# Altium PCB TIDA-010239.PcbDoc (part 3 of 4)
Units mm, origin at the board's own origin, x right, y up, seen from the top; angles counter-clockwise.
Board outline 160 x 175 mm, 4 copper layers (Top Layer, Inside 1, Inside 2, Bottom Layer), stack 1.787 mm thick; 299 components, 146 nets, 710 pads, 164 vias.
Unrouted connection lines stored in the file: 9.
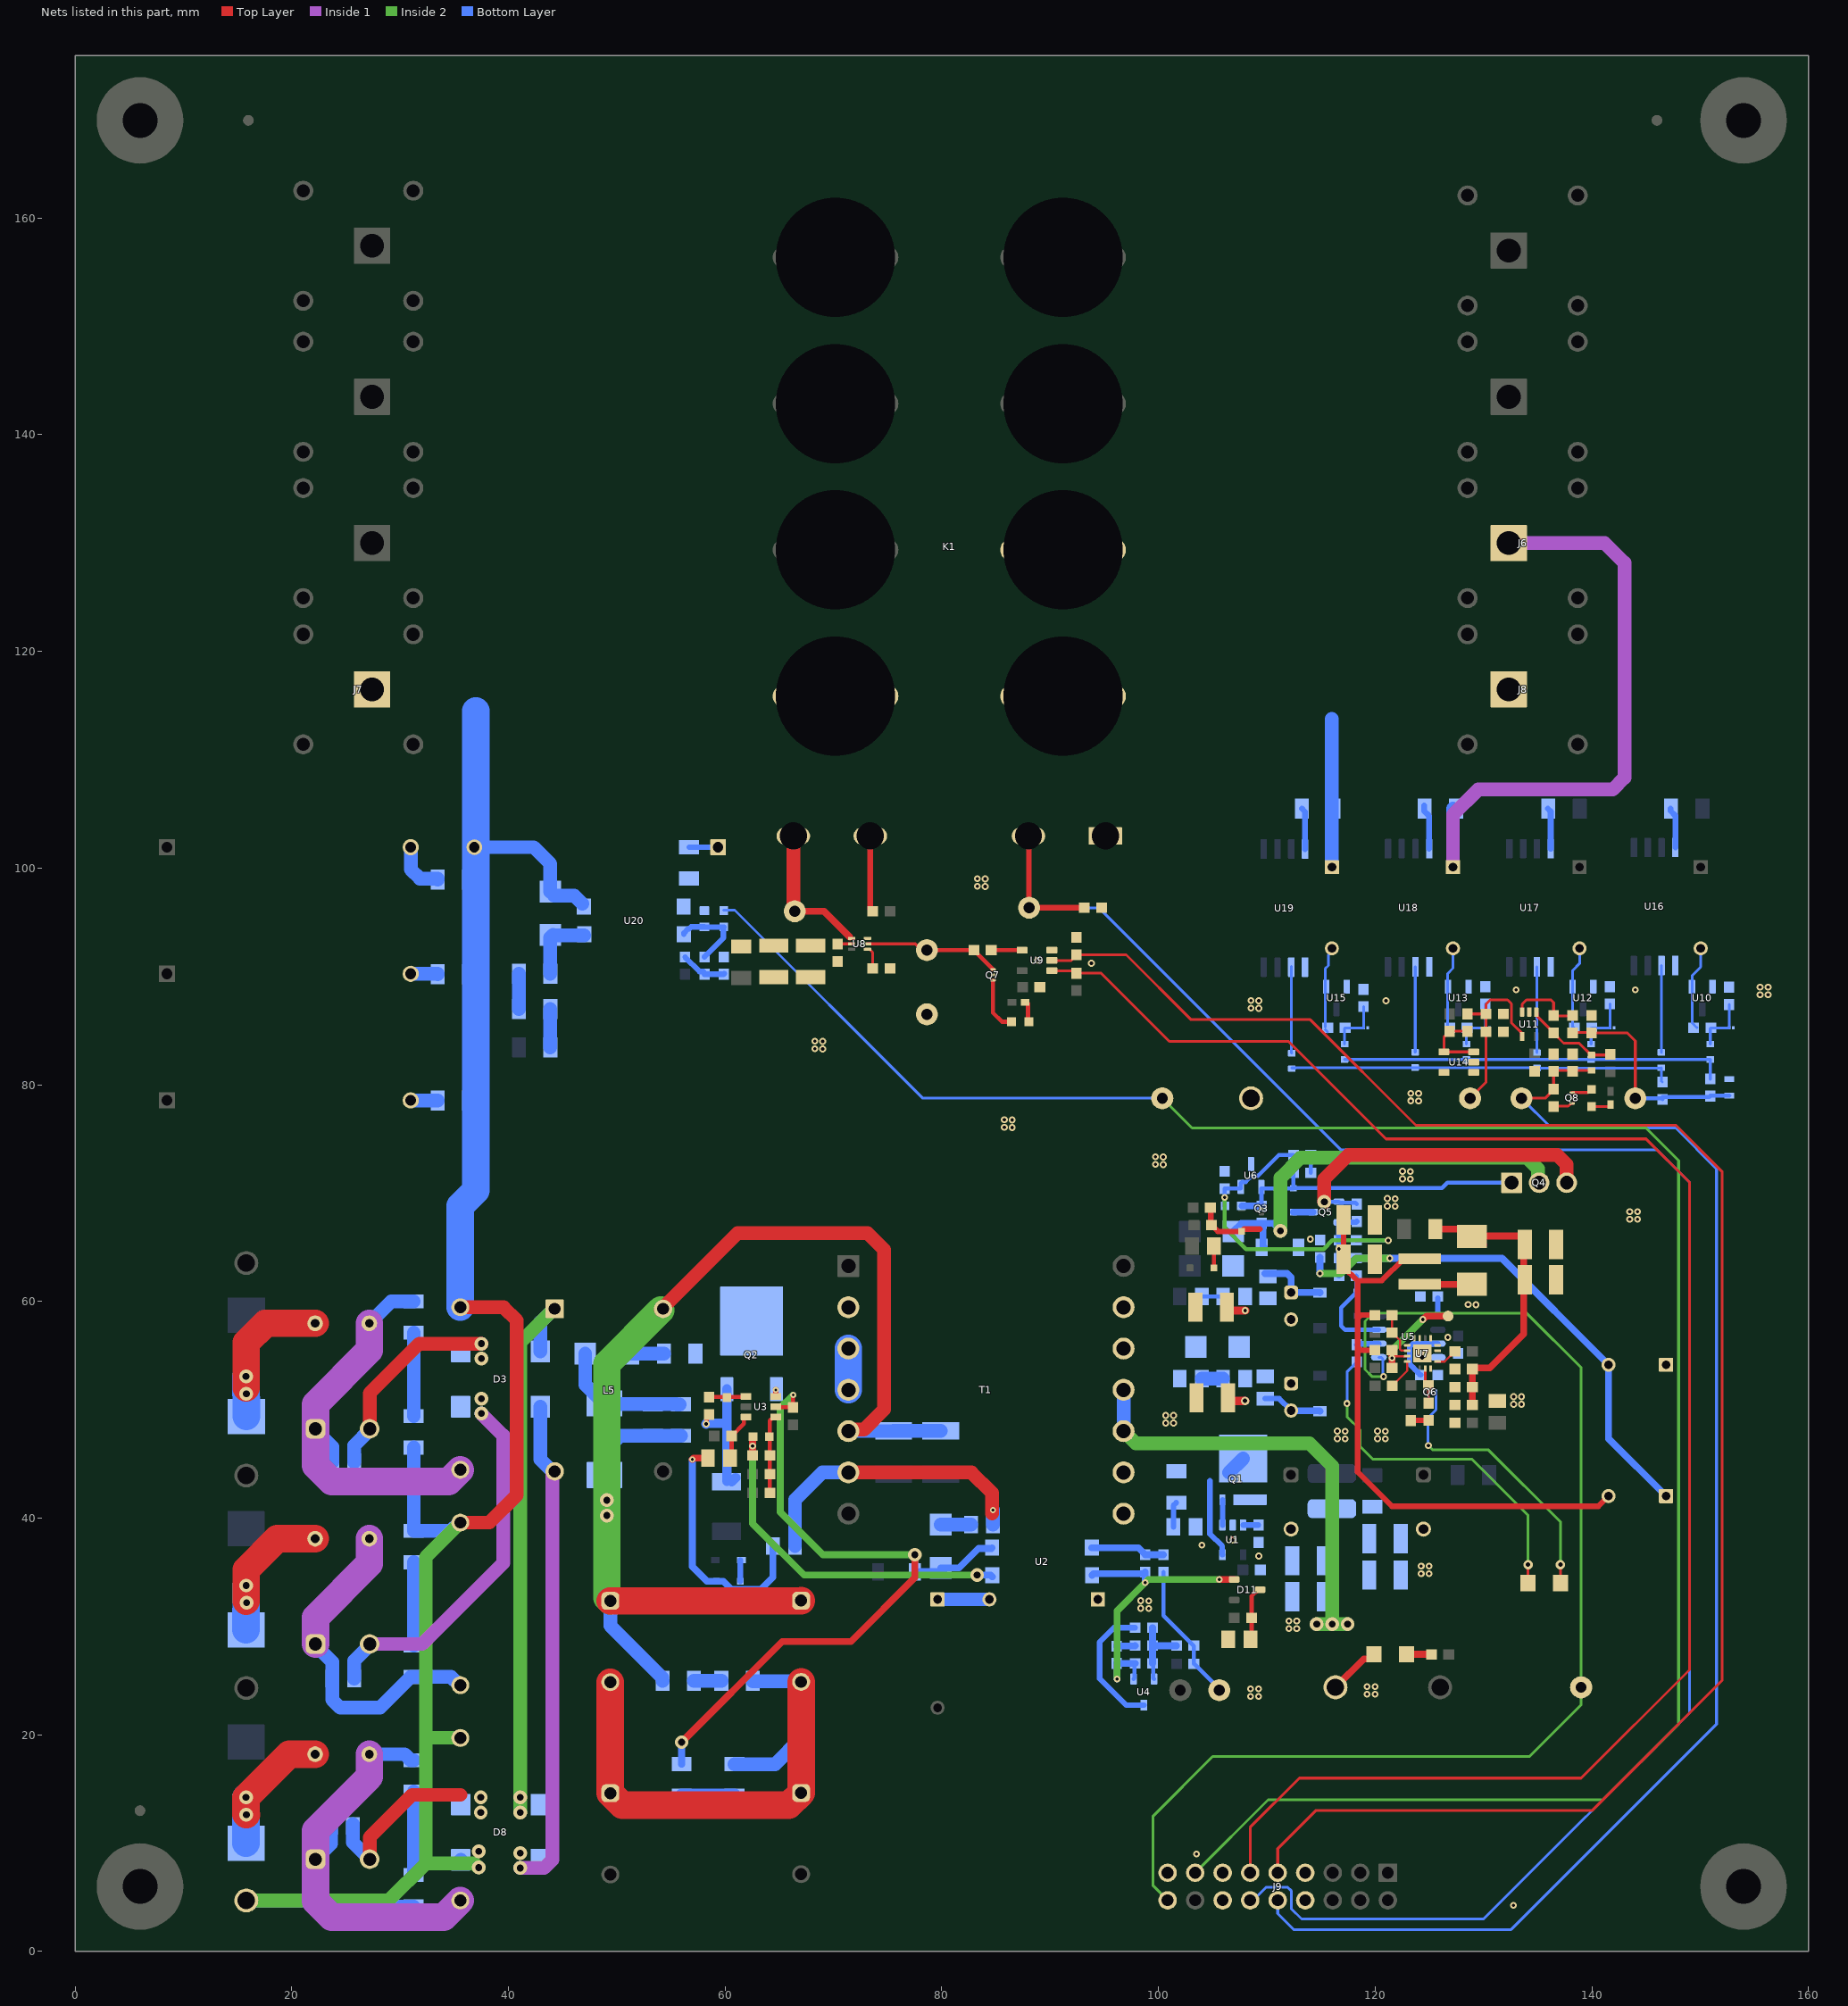
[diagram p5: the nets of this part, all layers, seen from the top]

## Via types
v1: diameter 0.635, hole 0.305, Top Layer to Bottom Layer, tented both sides, 118 vias
v2: diameter 1.27, hole 0.635, Top Layer to Bottom Layer, tented both sides, 35 vias
v3: diameter 0.762, hole 0.406, Top Layer to Bottom Layer, tented both sides, 4 vias
v4: diameter 0.559, hole 0.254, Top Layer to Bottom Layer, tented both sides, 4 vias
v5: diameter 0.864, hole 0.406, Top Layer to Bottom Layer, tented both sides, 3 vias

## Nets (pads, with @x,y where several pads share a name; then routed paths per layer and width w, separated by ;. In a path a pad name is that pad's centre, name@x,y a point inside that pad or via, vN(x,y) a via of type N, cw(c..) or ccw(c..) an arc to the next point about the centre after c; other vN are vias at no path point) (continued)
LINE3_OUT: C69.1 J6.1 K1.3 R89.2 | length 58.7
  Inside 1 w1.27: C69.1@127.176,100.08 127.176,104.926 129.5,107.25 141.922,107.25 143,108.328 143,128.172 141.182,129.99 J6.1@132.322,129.99
  Bottom Layer w1.27: C69.1@127.176,100.08 R89.2@127.176,105.474
MIRROR_IN: K1.11 R57.2 | length 7.1
  Top Layer w0.508: K1.11@73.394,102.958 73.394,96.228 R57.2@73.622,96 R57.2@73.612,96.01
N_IN: C9.2 C15.2 C20.2 C57.2 D8.3 D35.2 J7.1 K1.9 R7.1 R12.1 R19.1 R59.1 R60.1 R61.1 TP5.1 U20.2 | length 184.6
  Top Layer w1.27: C15.2@35.563,39.585 38.238,39.585 40.773,42.12 40.773,58.25 39.563,59.46 C9.2@35.563,59.46
  Inside 2 w1.27: TP5.1@15.817,4.723 28.973,4.723 ; 28.963,4.713 28.973,4.723 ; C20.2@35.563,19.71 32.378,19.75 ; C15.2@35.563,39.585 32.378,36.4 32.378,19.75 ; C15.2@35.567,39.585 C15.2@35.567,39.598 ; v2(37.25,7.75) 36.872,8.128 32.378,8.128 ; 28.973,4.723 32.378,8.128 ; 32.378,8.128 32.378,19.75
  Bottom Layer w1.27: TP5.1@15.813,4.71 23.253,4.71 23.803,4.16 R19.1@31.263,4.16 ; R7.1@31.263,46.52 R12.1@31.263,38.83 34.706,38.83 35.461,39.585 C15.2@35.563,39.585 ; D8.3@35.598,8.46 35.598,8.393 D8.3@35.863,8.128 ; C57.2@37,101.918 42.332,101.918 43.864,100.386 D35.2@43.864,97.822 44.229,97.457 46.06,97.457 U20.2@46.804,96.713
  Bottom Layer w2.54: C9.2@35.563,59.46 35.563,68.813 37,70.25 37,101.918 37,114.5
  other v2: 37.25,9.25
N_OUT: C71.1 J8.1 K1.2 R90.2 | length 13.7
  Bottom Layer w1.27: C71.1@116,100.08 116,113.75
NetC1_1: C1.1 C5.1 D1.1 L1.1 | length 1.4
  Top Layer w0.762: C5.1@106.599,59.164 v1(107.989,59.164)
NetC1_2: C1.2 R1.2 | length 2
  Bottom Layer w0.381: R1.2@103.989,60.45 C1.2@105.957,60.45
NetC2_1: C2.1 C3.2 | length 4.8
  Bottom Layer w1.27: C2.1@79.6,32.5 C3.2@84.4,32.5
NetC4_1: C4.1 D2.2 L1.2 | length 6.6
  Top Layer w0.635: C4.1@112.233,60.83 C4.1@112.238,60.835
  Bottom Layer w0.635: L1.2@109.833,62.576 111.861,62.576 112.233,62.204 C4.1@112.233,60.83 112.248,60.816 114.889,60.816 D2.2@114.903,60.801
NetC6_1: C6.1 C7.1 C8.1 C13.1 C14.1 D4.2 L5.4 R4.2 R5.2 T1.5 | length 121.3
  Top Layer w1.27: L5.4@54.063,59.21 61.147,66.294 73.152,66.294 74.676,64.77 74.676,50.038 72.812,48.174 71.517,48.174 T1.5@71.373,48.03
  Top Layer w2.54: C13.1@49.403,32.36 66.987,32.36 C14.1@67.013,32.386
  Inside 2 w2.54: C13.1@49.403,32.36 49.083,32.68 v2(49.083,41.652) 49.083,54.23 L5.4@54.063,59.21
  Bottom Layer w1.27: v2(49.083,40.244) v2(49.083,41.652) 49.083,43.502 48.873,43.712 48.963,43.801 48.963,46.27 50.293,47.6 R4.2@55.918,47.6 ; C13.1@49.403,32.36 49.403,30.068 54.21,25.261 54.21,24.986 R5.2@54.225,24.971 ; T1.5@71.373,48.03 71.38,48.037 C7.1@75.551,48.037 ; C7.1@75.551,48.044 C6.1@79.891,48.044
NetC8_2: C8.2 D4.1 D7.1 R4.1 | length 12
  Bottom Layer w1.27: D7.1@47.083,55.17 47.083,52.311 D4.1@48.575,50.819 ; D4.1@48.873,50.849 49.207,50.515 53.163,50.515 55.514,50.515 55.529,50.5 R4.1@55.804,50.5
NetC9_1: C9.1 L2.1 R2.2 R3.1 RT1.2 | length 38.2
  Inside 1 w2.54: RT1.2@27.163,57.98 27.163,55.48 22.193,50.51 22.193,44.868 23.681,43.38 34.483,43.38 C9.1@35.563,44.46
  Bottom Layer w1.27: L2.1@22.193,48.24 22.193,48.137 23.737,46.593 R3.1@23.737,45.18 ; RT1.2@27.198,58.014 29.193,60.01 R2.2@31.263,60.01
NetC10_2: C10.2 C11.1 D5.2 L3.1 | length 1.7
  Top Layer w0.762: C10.2@106.5,51.1 106.5,50.889 106.569,50.82 v3(107.989,50.82)
NetC11_2: C11.2 R6.2 | length 2
  Bottom Layer w1.27: R6.2@103.989,52.89 C11.2@105.957,52.89
NetC12_2: C12.2 D6.1 L3.2 | length 5.6
  Top Layer w0.635: C12.2@112.233,49.93 C12.2@112.238,49.925
  Bottom Layer w0.508: L3.2@109.833,51.034 111.129,51.034 C12.2@112.233,49.93
  Bottom Layer w0.635: C12.2@112.233,49.93 112.266,49.897 114.871,49.897 D6.1@114.903,49.865
NetC13_2: C13.2 C14.2 C16.1 C17.1 R8.1 R13.2 | length 55.9
  Top Layer w2.54: C13.2@49.403,24.86 C16.1@49.403,14.61 50.513,13.5 65.873,13.5 C17.1@67.013,14.64 C14.2@67.013,24.886
  Bottom Layer w1.27: R13.2@60.873,17.29 64.619,17.29 66.959,19.631 66.959,24.833 C14.2@67.013,24.886 66.97,24.929 62.574,24.929 62.559,24.944 R8.1@62.559,24.971
NetC15_1: C15.1 L4.1 R9.2 R10.1 RT2.2 | length 31.6
  Inside 1 w2.54: L4.1@22.193,28.38 22.193,30.83 27.163,35.8 RT2.2@27.163,38.1
  Bottom Layer w1.27: L4.1@22.193,28.38 22.193,28.277 23.737,26.733 R10.1@23.737,24.719 ; R10.1@23.737,25.2 23.737,23.246 24.483,22.5 28.148,22.5 R9.2@30.973,25.325 ; R9.2@30.988,25.34 34.706,25.34 35.461,24.585 C15.1@35.563,24.585
NetC19_1: C19.1 U1.3 | length 1.4
  Bottom Layer w0.508: U1.3@107.803,39.36 C19.1@109.223,39.36
NetC20_1: C20.1 L6.1 R15.1 R16.2 RT3.2 | length 38.5
  Inside 1 w2.54: RT3.2@27.163,18.21 27.163,16.12 22.193,11.15 22.193,4.663 23.681,3.175 34.028,3.175 C20.1@35.563,4.71
  Bottom Layer w1.27: L6.1@22.193,8.417 L6.1@22.193,8.52 23.617,9.944 R15.1@23.617,11.777 ; RT3.2@27.212,18.21 30.428,18.21 30.988,17.65 R16.2@31.263,17.65
NetC21_2: C21.2 C22.2 C23.2 C24.2 L7.1 R18.1 T1.10 T1.11 | length 41.9
  Inside 2 w1.27: T1.10@96.773,48.03 97.913,46.89 113.943,46.89 116.027,44.807 v2(116.027,30.208) ; v2(114.603,30.208) v2(116.027,30.208) ; v2(117.45,30.208) v2(116.027,30.208)
  Bottom Layer w1.27: T1.11@96.758,51.855 T1.11@96.773,51.84 T1.10@96.773,48.03
NetC27_1: C27.1 R23.1 | length 2.4
  Bottom Layer w0.508: C27.1@101.377,39.18 101.377,41.154 R23.1@101.643,41.42
NetC28_1: C28.1 C29.1 D11.1 R25.2 U2.2 U4.1 | length 29
  Top Layer w0.635: v1(105.603,34.34) D11.1@106.983,34.34
  Inside 2 w0.635: v1(96.162,25.144) 96.162,31.432 v1(98.775,34.046) 99.069,34.34 v1(105.603,34.34)
  Bottom Layer w0.381: U4.1@97.693,25.144 97.768,25.219 97.768,26.515 C28.1@97.838,26.585
  Bottom Layer w0.635: U2.2@93.862,34.73 94.008,34.875 R25.2@98.618,34.875 ; C29.1@96.123,26.59 C29.1@96.128,26.585 ; v1(96.162,25.144) 96.162,26.552 C29.1@96.128,26.585 ; C28.1@97.838,26.585 C29.1@96.128,26.585 ; R25.2@98.763,35.02 R25.2@98.618,34.875 ; v1(98.775,34.046) 98.775,34.838 98.738,34.875 R25.2@98.618,34.875
NetC28_2: C28.2 R28.1 R30.2 R33.2 U4.2 | length 7
  Bottom Layer w0.381: C28.2@99.443,26.58 99.518,26.505 99.518,25.219 U4.2@99.593,25.144
  Bottom Layer w0.635: C28.2@99.443,26.58 R30.2@99.443,28.22 ; R33.2@99.443,29.88 R30.2@99.443,28.22 ; R28.1@101.657,28.22 R30.2@99.443,28.22
NetC29_2: C29.2 R30.1 | length 1.7
  Bottom Layer w0.635: C29.2@96.123,28.19 96.138,28.205 97.828,28.205 R30.1@97.843,28.22
NetC30_1: C30.1 C32.1 D10.1 R17.1 U2.4 U3.2 | length 69.8
  Top Layer w0.381: U3.2@64.678,50.28 64.713,50.245 66.238,50.245 C32.1@66.273,50.21 v4(66.273,51.36)
  Top Layer w0.635: v2(55.983,19.32) 65.283,28.62 71.613,28.62 77.513,34.52 v2(77.513,36.62)
  Inside 2 w0.635: v4(66.273,51.36) 65.088,50.175 65.088,40.545 69.013,36.62 v2(77.513,36.62)
  Bottom Layer w0.635: R17.1@55.983,17.29 v2(55.983,19.32) ; v2(77.513,36.62) C30.1@77.513,35.05 D10.1@80.193,35.05 ; D10.1@79.9,35.4 81.6,35.4 83.407,37.207 84.574,37.207 U2.4@84.637,37.27
NetC31_1: C31.1 D11.3 R31.2 | length 5.1
  Top Layer w0.381: C31.1@108.475,28.8 108.593,28.918 R31.2@108.593,30.81 108.593,32.8 109.183,33.39 D11.3@109.383,33.39
NetC33_1: C33.1 R34.1 U3.4 | length 3.4
  Top Layer w0.381: R34.1@58.524,51.17 58.554,51.2 61.898,51.2 U3.4@61.928,51.23
NetC34_1: C34.1 R36.2 U2.3 | length 33.1
  Top Layer w0.635: R36.2@62.533,45.792 v1(62.533,46.656) C34.1@62.533,47.52
  Inside 2 w0.635: v1(62.533,46.656) 62.533,39.5 67.288,34.745 v2(83.255,34.745)
  Bottom Layer w0.635: v2@83.25,34.75 83.26,34.74 84.503,34.74 U2.3@84.662,34.58
NetC34_2: C34.2 C35.2 R36.1 R37.2 U3.1 | length 7.3
  Top Layer w0.381: C35.2@64.133,42.33 R37.2@64.133,44.06 64.133,47.52 64.133,48.985 64.478,49.33 U3.1@64.678,49.33
NetC37_1: C37.1 D16.1 Q4.2 R40.1 | length 38.8
  Inside 2 w1.27: v2(111.253,66.52) 111.253,71.403 113.101,73.25 134.014,73.25 135.007,72.257 135.007,71.076 Q4.2@135.128,70.955
  Bottom Layer w0.635: D16.1@106.895,66.454 107.651,67.21 R40.1@109.503,67.21 ; C37.1@109.763,64.98 109.633,65.11 109.633,67.08 R40.1@109.503,67.21 ; v2@111.273,66.21 111.162,66.321 111.162,66.656 110.608,67.21 R40.1@109.503,67.21
NetC38_1: C38.1 D17.2 Q4.1 R40.2 R44.1 U6.1 | length 28.2
  Bottom Layer w0.381: R40.2@109.503,68.81 109.498,68.815 109.498,70.405 109.493,70.41 109.513,70.43 112.423,70.43 D17.2@112.443,70.45 ; R44.1@112.453,71.88 112.448,71.875 112.448,70.455 D17.2@112.443,70.45 ; Q4.1@132.588,70.955 126.669,70.955 126.163,70.45 D17.2@112.443,70.45
  Bottom Layer w0.635: C38.1@107.699,68.81 R40.2@109.503,68.81
NetC38_2: C38.2 C39.2 R43.2 R48.2 U6.2 | length 31.5
  Inside 2 w0.381: v1(106.099,69.61) 106.099,66.825 108.088,64.835 115.232,64.835 116.027,65.63 v1(121.202,65.63)
  Bottom Layer w0.381: C38.2@106.099,68.81 v1(106.099,69.61) R48.2@106.099,70.41 107.593,70.41 107.593,70.91 107.703,71.02 108.06,71.02 108.641,71.601 109.204,71.601 111.103,73.5 C39.2@112.453,73.5 ; R43.2@118.253,65.63 v1(121.202,65.63)
NetC39_1: C39.1 R44.2 | length 1.6
  Bottom Layer w0.381: R44.2@114.053,71.88 C39.1@114.053,73.5
NetC40_1: C40.1 C42.2 R46.1 R47.2 | length 50.2
  Inside 2 w0.635: v1(114.903,62.576) 116.829,62.576 118.233,63.98 v1(121.334,63.98)
  Bottom Layer w0.635: v1(114.903,62.576) R47.2@114.903,64.06 ; R46.1@118.253,63.98 v1(121.334,63.98) 131.703,63.98 C42.2@141.533,54.15 141.533,47.33 C40.1@146.833,42.03
NetC41_1: C41.1 U5.3 | length 5.7
  Bottom Layer w0.508: C41.1@124.183,53.22 124.158,53.22 123.937,53.441 123.937,53.466 123.173,54.23 123.173,55.784 123.482,56.092 125.766,56.092 U5.3@125.783,56.11
NetC44_1: C44.1 U5.1 | length 1.6
  Bottom Layer w0.508: U5.1@125.783,58.65 C44.1@125.783,60.296
NetC47_2: C47.2 R49.1 U7.2 | length 4.2
  Top Layer w0.203: R49.1@121.553,58.74 C47.2@121.553,57.119 121.578,57.119 122.282,56.415 122.282,55.587 122.401,55.468 122.935,55.468 U7.2@122.953,55.45
NetC48_2: C48.2 C49.2 C50.1 D20.1 L9.1 R51.2 R52.2 | length 28.2
  Top Layer w0.635: L9.1@125.553,66.67 128.293,66.67 128.923,66.04 133.567,66.04 133.7,65.908 133.7,65.25 133.7,62 133.7,56.987 130.579,53.866 129.069,53.866 C50.1@128.963,53.76 ; D20.1@128.926,66.005 129.688,65.243 D20.1@130.007,65.243 ; R52.2@128.963,50.43 R51.2@128.963,52.094 C50.1@128.963,53.76 ; C50.1@128.988,53.76 C50.1@128.963,53.76
NetC50_2: C50.2 R51.1 R52.1 R56.2 U7.8
NetC51_1: C51.1 R53.2 U7.7 | length 3.3
  Top Layer w0.254: U7.7@124.603,53.8 124.603,52.614 C51.1@124.913,52.266 124.919,51.918 124.919,50.986 R53.2@124.944,50.613
NetC52_1: C52.1 U7.4 | length 2.8
  Top Layer w0.203: C52.1@121.583,52.256 121.608,52.256 122.953,53.601 U7.4@122.953,54.45
NetC53_2: C53.2 R53.1 | length 1.7
  Top Layer w0.508: C53.2@123.273,49.006 123.276,49.01 124.941,49.01 R53.1@124.944,49.013
NetC54_2: C54.2 R59.2 | length 5
  Bottom Layer w1.27: C54.2@30.984,101.918 30.984,99.868 31.832,99.02 33.457,99.02 33.472,99.005 R59.2@33.472,98.93
NetC55_2: C55.2 R60.2 | length 2.5
  Bottom Layer w1.27: C55.2@30.984,90.234 33.457,90.234 33.472,90.219 R60.2@33.472,90.18
NetC56_2: C56.2 R61.2 | length 2.5
  Bottom Layer w1.27: C56.2@30.984,78.55 R61.2@33.472,78.55
NetC57_1: C57.1 R62.2 | length 2.8
  Bottom Layer w0.508: R62.2@56.672,101.93 56.678,101.924 59.346,101.924 C57.1@59.422,102
NetC58_2: C58.2 C59.2 C60.1 F4.1 U8.5 | length 1.3
  Top Layer w0.254: C60.1@70.4,92.976 70.424,93 U8.5@71.666,93
NetC62_2: C62.2 R68.1 U10.1 | length 7.8
  Bottom Layer w0.254: R68.1@149.697,85.275 149.672,85.275 149.247,85.7 149.247,88.925 149.247,90.075 150.036,90.864 C62.2@150.036,92.58
NetC63_1: C63.1 D22.2 D23.1 R68.2 | length 5.4
  Bottom Layer w0.254: D22.2@150.922,83.75 150.922,85.2 R68.2@150.972,85.25 D23.1@152.672,85.25 C63.1@152.672,87.4
NetC65_2: C65.2 R72.1 U12.1 | length 7.7
  Bottom Layer w0.254: R72.1@138.222,85.309 138.222,88.899 138.222,90.55 138.86,91.188 C65.2@138.86,92.58 ; R72.1@138.272,85.309 R72.1@138.417,85.164
NetC66_1: C66.1 R70.2 R71.1 R74.2 R75.2 TP18.1 | length 20.1
  Top Layer w0.254: R71.1@138.213,84.824 139.918,84.824 R75.2@139.963,84.779 143.263,84.779 144,84.041 TP18.1@144,78.75
  Bottom Layer w0.381: TP18.1@144,78.75 146.4,78.75 R74.2@146.5,78.65 ; R74.2@146.5,78.873 150.845,78.873 R70.2@150.922,78.95 ; R70.2@150.926,78.992 152.669,78.992 C66.1@152.672,78.988
NetC68_1: C68.1 D25.2 D26.1 R72.2 | length 5.4
  Bottom Layer w0.254: D25.2@139.922,83.75 139.922,85.2 R72.2@139.972,85.25 D26.1@141.672,85.25 C68.1@141.672,87.45
NetC69_2: C69.2 R77.1 U13.1 | length 7.8
  Bottom Layer w0.254: R77.1@126.822,85.09 126.672,85.24 126.672,88.825 126.672,90.25 127.176,90.754 C69.2@127.176,92.58
NetC70_1: C70.1 D27.2 D28.1 R77.2 | length 5.4
  Bottom Layer w0.254: D27.2@128.422,83.75 128.422,85.2 R77.2@128.472,85.25 D28.1@130.172,85.25 C70.1@130.172,87.45
NetC71_2: C71.2 R80.1 U15.1 | length 7.8
  Bottom Layer w0.254: R80.1@115.397,85.078 R80.1@115.597,84.878 ; R80.1@115.397,85.328 115.397,88.828 115.397,90.725 115.672,91 115.672,91.969 116,92.297 C71.2@116,92.58
NetC72_1: C72.1 D29.2 D30.1 R80.2 | length 5.2
  Bottom Layer w0.254: D29.2@117.172,83.75 117.172,85.2 R80.2@117.222,85.25 D30.1@118.922,85.25 C72.1@118.922,87.2
NetC74_1: C74.1 R39.1 R82.2 | length 4.1
  Bottom Layer w0.508: R39.1@56.31,91.796 56.31,91.771 57.639,90.442 R82.2@57.98,90.442 ; R82.2@58.088,90.196 C74.1@59.866,90.196 59.868,90.196 C74.1@59.922,90.25
NetC75_1: C75.1 R83.2 | length 3.6
  Bottom Layer w1.27: C75.1@43.864,83.434 R83.2@43.864,87.001
NetC76_1: C76.1 C77.2 R82.1 U20.4 | length 7.5
  Bottom Layer w0.508: U20.4@56.197,93.89 56.197,93.99 56.593,94.386 56.693,94.386 56.871,94.564 C77.2@58.088,94.564 58.113,94.539 59.883,94.539 59.842,94.498 59.842,93.55 58.334,92.042 58.309,92.042 58.088,91.821 R82.1@58.088,91.796
NetD3_1: D3.1 D8.1 L5.1 | length 51.9
  Inside 2 w1.27: v2(41.103,12.84) 41.103,56.25 L5.1@44.063,59.21
  Bottom Layer w1.27: D3.1@42.948,55.38 42.948,58.095 L5.1@44.063,59.21
  other v2: 41.103,14.22
NetD3_2: D3.2 D8.2 L5.2 | length 45.5
  Inside 1 w1.27: v2(41.103,7.71) 43.295,7.71 44.063,8.478 L5.2@44.063,44.21
  Bottom Layer w1.27: D3.2@42.948,50.28 42.948,45.414 44.063,44.299 L5.2@44.063,44.21
  other v2: 41.103,9.09
NetD3_3: D3.3 L4.2 R10.2 | length 33.8
  Inside 1 w1.27: L4.2@27.193,28.38 32.043,28.38 39.513,35.85 39.513,47.64 v2(37.503,49.65)
  Bottom Layer w1.27: R10.2@25.769,25.2 25.769,26.853 27.193,28.277 L4.2@27.193,28.38
  other v2: 37.503,51.03
NetD3_4: D3.4 L2.2 R3.2 | length 19.1
  Top Layer w1.27: L2.2@27.193,48.24 27.193,51.52 31.773,56.1 v2(37.503,56.1)
  Bottom Layer w1.27: R3.2@25.769,45.18 25.769,46.713 27.193,48.137 L2.2@27.193,48.24
  other v2: 37.503,54.72
NetD5_1: D5.1 R6.1 T1.12
NetD7_2: D7.2 R11.2 | length 3.3
  Bottom Layer w1.27: D7.2@51.083,55.17 R11.2@54.363,55.17
NetD8_4: D8.4 L6.2 R15.2 | length 16
  Top Layer w1.27: L6.2@27.193,8.52 27.193,10.54 31.113,14.46 35.563,14.46
  Bottom Layer w1.27: R15.2@25.649,11.777 25.649,10.064 L6.2@27.193,8.52 L6.2@27.193,8.417
  other v2: 37.443,12.84 37.443,14.22
NetD9_2: D9.2 R20.1 | length 2.3
  Top Layer w0.635: D9.2@122.888,27.432 R20.1@125.184,27.432
NetD10_2: D10.2 R24.1 | length 2.8
  Bottom Layer w1.27: D10.2@79.9,39.4 R24.1@82.684,39.4
NetD12_1: D12.1 R27.1 R29.2 | length 23
  Top Layer w0.635: v4(56.973,45.414) 57.099,45.54 R29.2@58.417,45.54
  Bottom Layer w0.635: v4(56.973,45.414) 56.973,35.527 58.33,34.17 59.83,34.17 60.574,33.426 63.301,33.426 64.417,34.542 R27.1@64.417,37.41
NetD12_2: D12.2 D13.2 | length 1.9
  Bottom Layer w0.508: D12.2@61.403,34.17 D13.2@61.403,36.12
NetD14_1: D14.1 R21.1 | length 2.1
  Top Layer w0.381: D14.1@105.113,63.09 105.113,64.854 R21.1@105.359,65.1
NetD17_1: D17.1 Q5.3 | length 1.8
  Bottom Layer w0.635: D17.1@112.443,68.25 Q5.3@114.243,68.25
NetD18_2: D18.2 R45.2 U5.7 | length 8.9
  Bottom Layer w0.381: R45.2@118.253,62.37 118.273,62.35 118.273,60.881 D18.2@118.293,60.861 116.853,59.421 116.853,57.75 117.223,57.38 U5.7@120.333,57.38
NetD19_1: D19.1 Q6.3@125.605,51.646 | length 26
  Top Layer w0.254: D19.1@137.1,34 v5(137.1,35.7)
  Inside 2 w0.254: v1(124.9,46.7) 124.908,46.7 125.316,46.292 130.458,46.292 137.1,39.65 v5(137.1,35.7)
  Bottom Layer w0.254: v1(124.9,46.7) 124.867,46.733 124.867,49.257 125.605,49.995 Q6.3@125.605,51.646
NetD19_2: D19.2 R41.1 | length 33.1
  Top Layer w0.254: D19.2@134.1,34 v5(134.1,35.7)
  Inside 2 w0.254: v1(117.396,50.579) 117.396,49.354 118.6,48.15 118.6,46.6 119.766,45.434 128.935,45.434 134.1,40.269 v5(134.1,35.7)
  Bottom Layer w0.254: v1(117.396,50.579) 117.396,53.489 118.293,54.385 R41.1@118.293,54.41
NetD20_2: D20.2 L8.2 U7.1 U7.15 U7.16 | length 4.9
  Top Layer w0.635: L8.2@124.103,61.575 128.968,61.575 D20.2@128.973,61.57
NetD21_1: D21.1 Q7.3@84.734,89.635 | length 5
  Top Layer w0.381: Q7.3@84.734,89.635 84.734,86.635 85.554,85.815 D21.1@86.437,85.815
NetD21_2: D21.2 R63.1 | length 1.9
  Top Layer w0.381: R63.1@87.876,87.6 87.957,87.519 87.957,85.895 D21.2@88.037,85.815
NetD22_1: D22.1 D25.1 D27.1 D29.1 R70.1 | length 35.6
  Bottom Layer w0.254: D29.1@117.172,82.33 D27.1@128.422,82.33 D25.1@139.922,82.33 D22.1@150.922,82.33 R70.1@150.922,80.505
NetD24_2: D24.2 R69.1 R76.1 U11.1 | length 8.7
  Top Layer w0.254: U11.1@134.863,86.704 134.936,86.631 134.936,86.331 136.463,84.804 R76.1@136.463,84.779 ; R76.1@136.463,84.754 137.388,83.829 138.823,83.829 139.913,82.739 D24.2@139.963,82.739 141.663,82.739 R69.1@141.713,82.789
NetD31_2: D31.2 U16.6 | length 8
  Bottom Layer w0.254: D31.2@146.422,82.96 U16.6@146.422,91
NetD32_2: D32.2 U17.6 | length 7.9
  Bottom Layer w0.254: D32.2@134.923,82.961 U17.6@134.923,90.88
NetD33_2: D33.2 U18.6 | length 7.9
  Bottom Layer w0.254: D33.2@123.672,83 123.693,83.021 123.693,90.861 U18.6@123.714,90.882
NetD34_2: D34.2 U19.6 | length 8
  Bottom Layer w0.254: U19.6@112.25,90.935 U19.6@112.25,90.85 112.275,90.825 112.275,82.935 D34.2@112.3,82.91
NetD35_1: D35.1 R84.1 U20.1 | length 6.6
  Bottom Layer w1.27: R84.1@43.864,90.234 43.864,93.568 44.118,93.822 44.145,93.795 U20.1@46.992,93.795
NetD36_1: D36.1 Q8.3@138.182,79.279 | length 1.9
  Top Layer w0.254: Q8.3@138.182,79.279 139.663,79.279 D36.1@139.963,79.579 ; D36.1@139.938,79.354 D36.1@139.963,79.329
NetD36_2: D36.2 R85.1 | length 1.8
  Top Layer w0.254: D36.2@139.963,77.979 141.54,77.979 141.713,78.152 R85.1@141.713,78.179
NetF1_1: F1.1 RT1.1 | length 15
  Top Layer w2.54: v2@15.798,52.035 15.798,56.205 17.573,57.98 RT1.1@22.163,57.98
  Bottom Layer w2.54: v2(15.783,53.07) F1.1@15.813,49.385
  other v2: 15.813,51.48
NetF2_1: F2.1 RT2.1 | length 14.6
  Top Layer w2.54: v2@15.798,32.325 15.798,35.235 18.663,38.1 RT2.1@22.163,38.1
  Bottom Layer w2.54: F2.1@15.783,29.69 v2(15.798,33.78)
  other v2: 15.828,32.19
NetF3_1: F3.1 RT3.1 | length 13.9
  Top Layer w2.54: v2(15.813,12.63) 15.783,12.66 v2(15.783,14.22) 19.773,18.21 RT3.1@22.163,18.21
  Bottom Layer w2.54: F3.1@15.783,9.995 v2(15.783,14.22)
NetQ1_4: Q1.4 U1.1 | length 2.3
  Bottom Layer w0.508: U1.1@105.903,39.36 Q1.4@105.903,41.7
NetQ1_5-6-7-8: Q1.5-6-7-8 R23.2 T1.8 T1.9 U1.5 | length 9.2
  Bottom Layer w0.508: 104.744,43.444 104.744,38.544 105.875,37.413 105.875,36.638 U1.5@105.903,36.61
  Bottom Layer w1.27: Q1.5-6-7-8@106.508,44.2 Q1.5-6-7-8@107.808,45.5
NetQ2_1: Q2.1 U3.3 | length 0.6
  Top Layer w0.508: U3.3@64.678,51.23 v4(64.678,51.84)
NetQ2_3: Q2.3 R34.2 R35.2 | length 11.9
  Top Layer w0.381: v1(58.244,48.698) 58.293,48.747 58.293,49.339 R34.2@58.524,49.57
  Bottom Layer w0.889: v1(58.244,48.698) 58.296,48.75 60.164,48.75 ; R35.2@60.164,43.411 60.164,48.75 ; Q2.3@60.164,51.9 60.164,48.75 ; R35.2@60.608,43.37 R35.2@60.963,43.726
NetQ2_4: Q2.4 R11.1 T1.2
NetQ4_3: Q4.3 Q5.1 R42.2 | length 30.5
  Top Layer w1.27: v2(115.304,69.2) 115.304,71.304 117.5,73.5 136.812,73.5 137.668,72.644 Q4.3@137.668,70.955
  Bottom Layer w0.381: v2(115.304,69.2) Q5.1@116.643,69.2 116.753,69.091 118.183,69.091 R42.2@118.293,68.98
NetQ8_1: Q8.1@138.182,78.279 R86.2 | length 1.8
  Top Layer w0.254: R86.2@136.463,78.024 137.811,78.024 138.066,78.279 Q8.1@138.182,78.279
NetR2_1: R2.1 R7.2 | length 7.7
  Bottom Layer w1.27: R7.2@31.263,49.42 R2.1@31.263,57.11
NetR5_1: R5.1 R8.2 | length 2.5
  Bottom Layer w1.27: R5.1@57.125,24.971 R8.2@59.659,24.971
NetR9_1: R9.1 R12.2 | length 7.7
  Bottom Layer w1.27: R9.1@31.263,28.24 R12.2@31.263,35.93
NetR13_1: R13.1 R17.2 | length 4.9
  Bottom Layer w1.27: R17.2@55.983,14.39 R13.1@60.873,14.39
NetR16_1: R16.1 R19.2 | length 7.7
  Bottom Layer w1.27: R19.2@31.263,7.06 R16.1@31.263,14.75
NetR22_1: R22.1 R26.2 R28.2 TP7.1 | length 13.1
  Bottom Layer w0.381: R26.2@100.443,35.02 100.443,31.009 103.257,28.195 R22.1@103.257,26.56 ; R22.1@103.257,26.56 103.282,26.56 105.603,24.239 TP7.1@105.603,24.12
NetR24_2: R24.2 R27.2 T1.6 | length 27.6
  Top Layer w1.27: T1.6@71.373,44.22 82.739,44.22 84.629,42.33 84.629,40.41
  Bottom Layer w1.27: R27.2@66.449,37.41 66.449,41.696 68.973,44.22 T1.6@71.373,44.22 ; R24.2@84.716,39.4 v4(84.716,40.75)
NetR25_1: R25.1 R26.1 U2.1 | length 6.9
  Bottom Layer w0.635: U2.1@93.837,37.27 98.138,37.27 98.763,36.645 R25.1@98.763,36.62 R26.1@100.443,36.62
NetR29_1: R29.1 R32.2 U3.6 | length 4.5
  Top Layer w0.381: R29.1@60.449,45.54 60.593,45.684 R32.2@60.593,47.58 60.618,47.58 61.74,48.702 61.74,49.221 61.85,49.33 U3.6@61.928,49.33
NetR41_2: R41.2 U5.6 | length 2.1
  Bottom Layer w0.508: R41.2@118.293,56.01 118.375,56.092 120.316,56.092 U5.6@120.333,56.11
NetR50_1: R50.1 R54.2 TP11.1 U7.3 | length 9.7
  Top Layer w0.203: v1@121.553,54.95 U7.3@122.953,54.95
  Top Layer w0.635: R54.2@121.553,53.88 v1(121.553,54.759) v1@121.553,54.95 ; v1(124.397,58.33) 124.717,58.65 TP11.1@126.723,58.65
  Inside 2 w0.635: v1(121.553,54.759) 121.553,55.486 v1(124.397,58.33)
NetR55_2: R55.2 U7.9 | length 2
  Top Layer w0.203: U7.9@125.753,54.45 126.408,54.45 127.338,55.38 R55.2@127.363,55.38
NetR64_1: R64.1 U8.1 | length 2.1
  Top Layer w0.254: U8.1@73.146,92.5 73.331,92.5 73.622,92.209 R64.1@73.622,90.75
NetR67_1: R67.1 U9.4 | length 2.9
  Top Layer w0.381: R67.1@84.556,92.43 84.561,92.425 87.406,92.425 U9.4@87.411,92.42
NetR71_2: R71.2 R76.2 U11.3 | length 6.9
  Top Layer w0.254: U11.3@133.563,86.704 133.563,87.429 133.963,87.829 136.213,87.829 136.463,87.579 R76.2@136.463,86.379 136.508,86.334 R71.2@138.213,86.334
NetR78_1: R78.1 R79.2 U14.3 U14.4 | length 6.5
  Top Layer w0.254: R79.2@128.507,84.929 R78.1@126.86,84.929 126.86,84.904 126.338,84.381 U14.4@126.338,83.029 U14.3@129.088,83.029
NetR83_1: R83.1 R84.2 | length 3.2
  Bottom Layer w1.27: R83.1@40.964,87.001 R84.2@40.964,90.234
NetR87_1: R87.1 U16.4 | length 3.8
  Bottom Layer w0.54: R87.1@147.25,105.5 147.25,105.275 147.692,104.833 U16.4@147.692,101.9
NetR88_1: R88.1 U17.4 | length 3.8
  Bottom Layer w0.54: R88.1@135.932,105.474 136.193,105.213 U17.4@136.193,101.78
NetR89_1: R89.1 U18.4 | length 4.2
  Bottom Layer w0.54: R89.1@124.5,105.75 124.5,105.275 124.984,104.791 U18.4@124.984,101.782
NetR90_1: R90.1 U19.4 | length 3.9
  Bottom Layer w0.54: R90.1@113.222,105.5 113.52,105.202 U19.4@113.52,101.75
NetT1_3: T1.3 T1.4 | length 3.8
  Bottom Layer w2.54: T1.4@71.373,51.84 T1.3@71.373,55.65
PGND: C3.1 C4.2 C5.2 C10.1 C12.1 C18.2 C19.2 C21.1 C22.1 C23.1 C24.1 C25.2 C26.2 C27.2 C31.2 C36.2 C37.2 C41.2 C42.1 C43.2 C44.2 C45.1 C46.1 C48.1 C49.1 C58.1 C59.1 C60.2 C61.2 C63.2 C64.2 C66.2 C67.2 C68.2 C70.2 C72.2 C73.2 C74.2 C77.1 D9.1 D15.2 D23.2 D26.2 D28.2 D30.2 J9.7 J9.8 J9.13 J9.14 J9.17 K1.1 NT1.2 Q1.1-2-3 Q3.2@109.503,68.56 Q6.2@125.105,51.646 Q7.2@84.734,90.135 Q8.2@138.182,78.779 R33.1 R38.1 R47.1 R48.1 R58.2 R62.1 R64.2 R66.1 R73.1 R75.1 R81.1 T1.13 TP8.1 TP9.1 TP22.1 U1.2 U4.3 U5.4 U6.3 U7.11 U7.12 U7.13 U7.17@124.353,55.2 U8.3 U9.3 U10.2 U11.2 U12.2 U13.2 U14.1 U14.2 U14.5 U15.2 U16.5 U17.5 U18.5 U19.5 U20.3 | length 23.6
  Top Layer w0.508: C36.2@104.783,68.67 104.829,68.625 104.829,67.088 R38.1@104.874,67.042 104.899,67.042 105.481,66.46 D15.2@107.673,66.46 107.883,66.67 109.353,66.67
  Top Layer w0.635: TP8.1@116.332,24.384 118.947,26.999 119.505,26.999 119.888,27.382 D9.1@119.888,27.432
  Bottom Layer w0.508: R33.1@97.843,29.88 95.88,29.88 94.56,28.56 94.56,25.19 97.006,22.744 U4.3@98.643,22.744
  other v1: 132.75,4.25 103.5,9 108.5,23.552 109.229,23.541 119.25,23.75 119.979,23.739 109.229,24.242 108.5,24.25 119.979,24.44 119.25,24.448 112.75,29.799 112.021,29.81 112.021,30.508 112.75,30.5 98.361,31.677 99.09,31.666 99.09,32.367 98.361,32.375 124.968,34.859 124.239,34.87 124.239,35.568 124.968,35.56 109.25,36.5 104,37.5 106.853,37.985 116.494,47.332 117.223,47.321 120.213,47.332 120.942,47.321 116.494,48.03 117.223,48.022 120.213,48.03 120.942,48.022 100.66,48.78 101.389,48.769 100.66,49.478 101.389,49.47 133.5,50.5 132.771,50.511 132.771,51.209 133.5,51.201 126.693,56.68 129.3,59.7 128.571,59.708 114,65.75 144.215,67.576 143.486,67.587 143.486,68.285 144.215,68.277 121.847,68.786 121.118,68.797 121.118,69.495 121.847,69.487 122.521,71.31 123.25,71.299 122.521,72.008 123.25,72 99.714,72.645 100.443,72.635 100.443,73.335 99.714,73.343 85.771,76.06 86.5,76.049 85.771,76.758 86.5,76.75 123.271,78.511 124,78.5 123.271,79.209 124,79.201 69,83.299 68.271,83.31 68.271,84.008 69,84 109.25,87.049 108.521,87.06 108.521,87.758 109.25,87.75 121,87.75 156.25,88.299 155.521,88.31 133,88.75 144,88.75 155.521,89.008 156.25,89 93.8,91.2 88.786,91.47 83.271,98.31 84,98.299 83.271,99.008 84,99
  other v3: 124.316,54.84
PLC_ZC_IN: C76.2 J9.15 TP15.1 | length 200
  Inside 2 w0.254: TP15.1@100.348,78.75 103.098,76 145,76 148,73 148,21 141,14 110.11,14 J9.15@103.38,7.27
  Bottom Layer w0.254: C76.2@59.866,96.114 60.886,96.114 78.25,78.75 TP15.1@100.348,78.75
R_ENABLE: J9.9 R66.2 U9.2 | length 167
  Top Layer w0.254: U9.2@90.161,91.47 91.944,91.47 92.434,91.96 R66.2@92.434,91.985 97.015,91.985 103,86 114,86 123.75,76.25 147.75,76.25 152,72 152,25 140,13 114.5,13 111,9.5 J9.9@111,7.27
R_MIRROR_OUT: J9.12 K1.12 R58.1 TP12.1 | length 183.3
  Top Layer w0.254: R58.1@93.14,96.33 R58.1@93.165,96.33
  Top Layer w0.508: K1.12@87.994,102.958 88.027,102.925 88.027,96.363 TP12.1@88.06,96.33 R58.1@93.14,96.33
  Bottom Layer w0.254: TP12.1@88.06,96.33 94.47,96.33 116.8,74 146,74 149,71 149,22 130,3 113.201,3 112.243,3.959 112.243,5.609 111.936,5.915 109.915,5.915 108.73,4.73 J9.12@108.46,4.73
RCD_nFAULT: J9.11 R92.1 U9.1 | length 162.7
  Top Layer w0.254: U9.1@90.161,90.52 92.198,90.52 R92.1@92.434,90.285 94.715,90.285 101,84 112,84 121,75 145,75 149,71 149,26 139,16 113,16 108.46,11.46 J9.11@108.46,7.27
Ref_0.2V: C73.1 R79.1 R81.2 TP21.1 U11.4 | length 17.1
  Top Layer w0.254: R79.1@128.507,86.529 130.21,86.529 C73.1@130.219,86.538 ; TP21.1@128.75,78.75 130.219,80.219 R81.2@130.219,84.888 C73.1@130.219,86.538 ; U11.4@133.528,84.489 133.49,84.527 133.49,84.802 132.559,85.733 132.559,85.943 132.573,85.958 132.573,87.468 132.213,87.829 130.617,87.829 130.219,87.431 C73.1@130.219,86.538
RELAY_CHECK: C67.1 D24.1 J9.10 R73.2 R86.1 TP16.1 | length 130.7
  Top Layer w0.254: TP16.1@133.5,78.75 135.679,78.75 136.463,79.534 R73.2@136.463,81.229 136.553,81.319 D24.1@139.963,81.319
  Bottom Layer w0.254: J9.10@111,4.73 111,3.5 112.468,2.032 132.545,2.032 151.5,20.987 151.5,72.243 147.743,76 136.25,76 TP16.1@133.5,78.75
RELAY_OH: K1.10 TP13.1 U8.4 | length 13.1
  Top Layer w0.635: TP13.1@66.422,96 69.126,96 U8.4@71.485,93.64
  Top Layer w1.27: K1.10@66.294,102.958 66.294,96.128 TP13.1@66.422,96
RELAY_STATE: Q7.1@84.734,90.635 R67.2 TP14.1 U8.2 | length 12.6
  Top Layer w0.254: U8.2@73.146,93 77.555,93 78.135,92.42 TP14.1@78.616,92.42
  Top Layer w0.381: TP14.1@78.616,92.42 78.621,92.425 82.951,92.425 R67.2@82.956,92.43 ; R67.2@82.956,92.412 82.999,92.412 83.266,92.146 83.266,92.103 Q7.1@84.734,90.635
Super_Cap_Char: J9.18 TP10.1 U5.5 | length 114.1
  Inside 2 w0.254: J9.18@100.84,4.73 99.5,6.07 99.5,12.5 105,18 134.25,18 139,22.75 139,53.901 134,58.902 119.79,58.902 119.052,58.163 119.052,53.725 119.725,53.052 v1(120.765,53.052)
  Bottom Layer w0.254: U5.5@120.333,54.84 120.539,54.84 120.698,54.68 120.698,53.119 v1(120.765,53.052)
Vbackup: C40.2 C45.2 C46.2 L8.1 Q5.2 R42.1 R43.1 R45.1 R46.2 R49.2 R50.2 | length 65.3
  Top Layer w0.508: C45.2@117.073,67.51 C46.2@117.073,63.892 117.073,63.192 118.345,61.92 ; R50.2@119.953,55.501 118.676,55.501 118.378,55.799 ; R49.2@119.953,58.74 118.676,58.74 118.378,58.442 ; L8.1@124.103,63.945 122.643,63.945 120.618,61.92 118.345,61.92 ; C40.2@141.533,42.03 140.593,41.089 121.541,41.089 118.378,44.253 118.378,55.799 ; 118.345,61.92 118.378,61.887 118.378,58.442 ; 118.378,55.799 118.378,58.442
  Bottom Layer w0.508: R45.1@116.653,62.37 116.648,62.375 116.648,67.295 Q5.2@116.643,67.3 118.213,67.3 R42.1@118.293,67.38
  other v1: 116.648,64.835
WD_RES_OUT: D31.1 D32.1 D33.1 D34.1 R74.1 | length 35.5
  Bottom Layer w0.254: D34.1@112.3,81.55 112.672,81.55 123.672,81.56 D32.1@134.922,81.56 ; 112.672,81.54 112.692,81.56 ; D32.1@134.922,81.54 146.382,81.54 D31.1@146.402,81.56 146.402,80.348 R74.1@146.5,80.25
pads on no net: FID1.1 FID2.1 FID3.1 H1.1 H2.1 H3.1 H4.1 J1.2 J1.3 J1.4 J1.5 J2.2 J2.3 J2.4 J2.5 J3.2 J3.3 J3.4 J3.5 J4.2 J4.3 J4.4 J4.5 J5.2 J5.3 J5.4 J5.5 J6.2 J6.3 J6.4 J6.5 J7.2 J7.3 J7.4 J7.5 J8.2 J8.3 J8.4 J8.5 LBL1.0 Q3.1@109.503,69.085 Q3.2@109.503,68.56 Q3.3@109.503,68.035 Q6.1@124.58,51.646 Q6.2@125.105,51.646 Q6.3@125.63,51.646 Q7.1@84.734,90.66 Q7.2@84.734,90.135 Q7.3@84.734,89.61 Q8.1@138.182,78.254 Q8.2@138.182,78.779 Q8.3@138.182,79.304 T1.1 U7.10 U7.14 U7.17@124.353,55.2 U8.6 U10.3 U12.3 U13.3 U15.3 U16.1 U16.2 U16.3 U16.7 U16.8 U17.1 U17.2 U17.3 U17.7 U17.8 U18.1 U18.2 U18.3 U18.7 U18.8 U19.1 U19.2 U19.3 U19.7 U19.8

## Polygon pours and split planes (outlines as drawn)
NetD12_1 on Top Layer "TOP_LAYER_NETD12_1_P014" (solid, remove dead copper, pour order 14): 56.523,46.656 56.523,44.06 58.829,44.06 59.055,44.286 59.055,46.408 58.807,46.656
NetD20_2 on Top Layer "TOP_LAYER_NETD20_2_P016" (solid, remove dead copper, pour order 16): 124.353,55.799 122.277,55.799 122.277,62.107 124.353,62.107
PGND on Top Layer "TOP_LAYER_PGND_P081" (solid, remove dead copper, pour order 81): 98.08,-0.001 98.082,-0.001 ccw(c98.081,-0.001) 98.081,0 160,0 160,91.75 ccw(c159.25,91.75) 159.25,92.5 103.79,92.5 cw(c103.79,95.04) 101.25,95.04 101.25,102.75 ccw(c99.5,102.75) 99.5,104.5 57.79,104.5 ccw(c57.79,101.96) 55.25,101.96 55.25,77.79 ccw(c57.79,77.79) 57.79,75.25 90.71,75.25 cw(c90.71,72.71) 93.25,72.71 93.5,2.5 ccw(c96,2.5) 96,0 98.081,0
PGND on Top Layer "TOP_LAYER_PGND_P021" (solid, remove dead copper, pour order 21): 123.573,54.39 125.043,54.39 125.163,54.51 125.163,55.11 125.373,55.32 126.153,55.32 127.023,56.19 127.023,56.813 126.866,56.97 124.983,56.97 124.953,56.94 124.953,56.22 124.743,56.01 123.573,56.01 123.543,55.98 123.543,54.408
AGND2 on Top Layer "TOP_LAYER_AGND2_P080" (solid, pour order 80): 118.676,57.809 122.013,57.809 122.023,56.079 128.09,56.091 128.09,57.691 128.208,57.809 129.394,57.809 129.564,57.64 129.564,49.758 132.06,49.758 132.06,46.592 118.676,46.592
NetC50_2 on Top Layer "Top Layer-NetC50_2" (solid, remove dead copper, pour order 75): 126.805,47.989 128.005,47.989 128.005,54.285 126.805,54.285 126.805,54.27 124.953,54.27 124.953,52.932 126.805,52.932
LINE1_OUT on Top Layer "TOP_LAYER_LINE1_OUT_P073" (solid, remove dead copper, pour order 73): 134.25,153 135.75,154.5 135.75,159.25 134.25,160.75 126.75,160.75 124.5,163 85,163 83.75,161.75 83.75,154.25 85,153
LINE2_OUT on Top Layer "TOP_LAYER_LINE2_OUT_P072" (solid, remove dead copper, pour order 72): 134.25,139.5 135.75,141 135.75,145.75 134.25,147.25 126.75,147.25 124.5,149.5 85,149.5 83.75,148.25 83.75,140.75 85,139.5
N_OUT on Top Layer "TOP_LAYER_N_OUT_P071" (solid, remove dead copper, pour order 71): 134.25,112.5 135.75,114 135.75,118.75 134.25,120.25 126.75,120.25 124.5,122.5 85,122.5 83.75,121.25 83.75,113.75 85,112.5
LINE3_OUT on Top Layer "TOP_LAYER_LINE3_OUT_P054" (solid, remove dead copper, pour order 54): 134.25,126 135.75,127.5 135.75,132.25 134.25,133.75 126.75,133.75 124.5,136 85,136 83.75,134.75 83.75,127.25 85,126
LINE1_IN on Top Layer "TOP_LAYER_LINE1_IN_P052" (solid, remove dead copper, pour order 52): 76.25,153 77.5,154.25 77.5,161.75 76.25,163 34.75,163 33,161.25 25,161.25 23.75,160 23.75,154.25 25,153
LINE2_IN on Top Layer "TOP_LAYER_LINE2_IN_P051" (solid, remove dead copper, pour order 51): 76.25,139.5 77.5,140.75 77.5,148.25 76.25,149.5 35.25,149.5 32.75,147 25,147 23.75,145.75 23.75,140.75 25,139.5
LINE3_IN on Top Layer "TOP_LAYER_LINE3_IN_P049" (solid, remove dead copper, pour order 49): 76.541,126.143 77.791,127.393 77.791,134.893 76.541,136.143 35.455,136.143 32.955,133.643 25.291,133.643 24.041,132.393 24.041,127.393 25.291,126.143
N_IN on Top Layer "TOP_LAYER_N_IN_P045" (solid, remove dead copper, pour order 45): 76.25,112.5 77.5,113.75 77.5,121.25 76.25,122.5 35.216,122.5 32.716,120 25,120 23.75,118.75 23.75,113.75 25,112.5
NetD3_3 on Top Layer "TOP_LAYER_NETD3_3_P042" (solid, remove dead copper, pour order 42): 34.918,51.93 34.558,51.57 34.558,49.08 34.888,48.75 37.888,48.75 38.188,49.05 38.188,51.63 37.888,51.93
NetD3_4 on Top Layer "TOP_LAYER_NETD3_4_P037" (solid, remove dead copper, pour order 37): 34.918,57 34.558,56.64 34.558,54.15 34.888,53.82 37.888,53.82 38.188,54.12 38.188,56.7 37.888,57
NetD8_4 on Top Layer "TOP_LAYER_NETD8_4_P032" (solid, remove dead copper, pour order 32): 34.858,15.12 34.498,14.76 34.498,12.27 34.828,11.94 37.828,11.94 38.128,12.24 38.128,14.82 37.828,15.12
GND on Top Layer "TOP_LAYER_GND_P025" (solid, remove dead copper, pour order 25): 57.633,52.86 56.523,51.75 56.523,38.28 57.033,37.77 72.633,37.77 73.053,38.19 73.053,41.66 72.712,42.03 68.038,42.03 67.416,42.458 67.395,52.121 66.656,52.86
NetC58_2 on Top Layer "TOP_LAYER_NETC58_2_P024" (solid, remove dead copper, pour order 24): 60.422,93.5 60.672,93.75 70.672,93.75 71.172,93.25 72.172,93.25 72.172,92.75 71.172,92.75 70.922,92.5 70.172,92.5 69.672,92 60.672,92 60.422,92.25
PGND on Bottom Layer "BOTTOM_LAYER_PGND_P076" (solid, remove dead copper, pour order 76): 98.08,-0.001 98.082,-0.001 ccw(c98.081,-0.001) 98.081,0 160,0 160,91.75 ccw(c159.25,91.75) 159.25,92.5 103.79,92.5 cw(c103.79,95.04) 101.25,95.04 101.25,102.75 ccw(c99.5,102.75) 99.5,104.5 57.79,104.5 ccw(c57.79,101.96) 55.25,101.96 55.25,77.79 ccw(c57.79,77.79) 57.79,75.25 90.71,75.25 cw(c90.71,72.71) 93.25,72.71 93.5,2.5 ccw(c96,2.5) 96,0 98.081,0
NetC1_1 on Bottom Layer "BOTTOM_LAYER_NETC1_1_P070" (solid, remove dead copper, pour order 70): 108.75,64.5 108.75,61.5 111.25,61.5 111.25,59 111,58.75 107,58.75 107,61.5 106.75,61.75 106,61.75 105.75,62 105.75,64.25 106,64.5
NetC10_2 on Bottom Layer "BOTTOM_LAYER_NETC10_2_P069" (solid, remove dead copper, pour order 69): 104.421,57.434 110.21,57.434 110.643,57 110.643,49.47 110.463,49.29 104.537,49.29 104.421,49.406
NetD5_1 on Bottom Layer "BOTTOM_LAYER_NETD5_1_P068" (solid, remove dead copper, pour order 68): 104.537,52.11 100.011,52.11 98.331,53.79 95.013,53.79 94.828,53.975 94.828,57.205 95.057,57.434 104.537,57.434
NetQ1_5-6-7-8 on Bottom Layer "BOTTOM_LAYER_NETQ1_5-6-7-8_P067" (solid, remove dead copper, pour order 67): 109.833,43.073 109.646,42.931 102.85,42.9 99.09,42.928 98.763,42.734 98.763,38.975 98.421,38.61 95.353,38.61 94.973,38.99 94.973,45.197 95.706,45.93 109.716,45.93 109.833,45.809
+14V_SW on Bottom Layer "BOTTOM_LAYER_+14V_SW_P066" (solid, remove dead copper, pour order 66): 104.099,59.726 103.833,59.46 100.443,59.46 100.133,59.77 100.133,60.87 99.713,61.29 94.973,61.29 94.583,61.68 94.583,67.76 95.073,68.25 103.593,68.25 104.099,67.744
LINE1_OUT on Bottom Layer "BOTTOM_LAYER_LINE1_OUT_P065" (solid, remove dead copper, pour order 65): 134.25,153 135.75,154.5 135.75,159.25 134.25,160.75 126.75,160.75 124.5,163 85,163 83.75,161.75 83.75,154.25 85,153
LINE2_OUT on Bottom Layer "BOTTOM_LAYER_LINE2_OUT_P064" (solid, remove dead copper, pour order 64): 134.25,139.5 135.75,141 135.75,145.75 134.25,147.25 126.75,147.25 124.5,149.5 85,149.5 83.75,148.25 83.75,140.75 85,139.5
LINE3_OUT on Bottom Layer "BOTTOM_LAYER_LINE3_OUT_P063" (solid, remove dead copper, pour order 63): 134.25,126 135.75,127.5 135.75,132.25 134.25,133.75 126.75,133.75 124.5,136 85,136 83.75,134.75 83.75,127.25 85,126
N_OUT on Bottom Layer "BOTTOM_LAYER_N_OUT_P058" (solid, remove dead copper, pour order 58): 134.25,112.5 135.75,114 135.75,118.75 134.25,120.25 126.75,120.25 124.5,122.5 85,122.5 83.75,121.25 83.75,113.75 85,112.5
LINE1_IN on Bottom Layer "BOTTOM_LAYER_LINE1_IN_P044" (solid, remove dead copper, pour order 44): 76.25,153 77.5,154.25 77.5,161.75 76.25,163 34.75,163 33,161.25 25,161.25 23.75,160 23.75,154.25 25,153
LINE2_IN on Bottom Layer "BOTTOM_LAYER_LINE2_IN_P041" (solid, remove dead copper, pour order 41): 76.25,139.5 77.5,140.75 77.5,148.25 76.25,149.5 35.25,149.5 32.75,147 25,147 23.75,145.75 23.75,140.75 25,139.5
LINE3_IN on Bottom Layer "BOTTOM_LAYER_LINE3_IN_P034" (solid, remove dead copper, pour order 34): 76.541,126.143 77.791,127.393 77.791,134.893 76.541,136.143 35.541,136.143 33.041,133.643 25.291,133.643 24.041,132.393 24.041,127.393 25.291,126.143
N_IN on Bottom Layer "BOTTOM_LAYER_N_IN_P033" (solid, remove dead copper, pour order 33): 76.25,112.5 77.5,113.75 77.5,121.25 76.25,122.5 35.216,122.5 32.716,120 25,120 23.75,118.75 23.75,113.75 25,112.5
NetQ2_4 on Bottom Layer "BOTTOM_LAYER_NETQ2_4_P028" (solid, remove dead copper, pour order 28): 56.523,56.7 56.163,56.34 56.163,54.102 56.417,53.848 67.564,53.848 68.072,54.356 68.072,57.404 68.326,57.658 71.882,57.658 72.39,58.166 72.39,60.96 71.882,61.468 56.973,61.41 56.523,60.96
NetD3_3 on Bottom Layer "BOTTOM_LAYER_NETD3_3_P027" (solid, remove dead copper, pour order 27): 34.953,51.93 34.593,51.57 34.593,49.08 34.923,48.75 37.923,48.75 38.223,49.05 38.223,51.63 37.923,51.93
NetD3_4 on Bottom Layer "BOTTOM_LAYER_NETD3_4_P026" (solid, remove dead copper, pour order 26): 34.953,57 34.593,56.64 34.593,54.15 34.923,53.82 37.923,53.82 38.223,54.12 38.223,56.7 37.923,57
NetD3_2 on Bottom Layer "BOTTOM_LAYER_NETD3_2_P020" (solid, remove dead copper, pour order 20): 43.653,10.05 44.013,9.69 44.013,7.2 43.683,6.87 40.683,6.87 40.383,7.17 40.383,9.75 40.683,10.05
NetD3_1 on Bottom Layer "BOTTOM_LAYER_NETD3_1_P019" (solid, remove dead copper, pour order 19): 43.653,15.12 44.013,14.76 44.013,12.27 43.683,11.94 40.683,11.94 40.383,12.24 40.383,14.82 40.683,15.12
N_IN on Bottom Layer "BOTTOM_LAYER_N_IN_P018" (solid, remove dead copper, pour order 18): 34.893,10.05 34.533,9.69 34.533,7.2 34.863,6.87 37.863,6.87 38.163,7.17 38.163,9.75 37.863,10.05
NetD8_4 on Bottom Layer "BOTTOM_LAYER_NETD8_4_P017" (solid, remove dead copper, pour order 17): 34.893,15.12 34.533,14.76 34.533,12.27 34.863,11.94 37.863,11.94 38.163,12.24 38.163,14.82 37.863,15.12
NetC21_2 on Bottom Layer "BOTTOM_LAYER_NETC21_2_P008" (solid, remove dead copper, pour order 8): 114.3,29.464 119.888,29.464 120.848,30.424 120.848,41.783 113.919,41.783 113.792,41.656 113.792,29.972 113.792,41.656 113.792,29.972
PGND on Inside 1 "INSIDE_1_PGND_P077" (solid, remove dead copper, pour order 77): 98.08,-0.001 98.082,-0.001 ccw(c98.081,-0.001) 98.081,0 160,0 160,91.75 ccw(c159.25,91.75) 159.25,92.5 103.79,92.5 cw(c103.79,95.04) 101.25,95.04 101.25,102.75 ccw(c99.5,102.75) 99.5,104.5 57.79,104.5 ccw(c57.79,101.96) 55.25,101.96 55.25,77.79 ccw(c57.79,77.79) 57.79,75.25 90.71,75.25 cw(c90.71,72.71) 93.25,72.71 93.5,2.5 ccw(c96,2.5) 96,0 98.081,0
N_OUT on Inside 1 "INSIDE_1_N_OUT_P057" (solid, remove dead copper, pour order 57): 134.25,112.5 135.75,114 135.75,118.75 134.25,120.25 126.75,120.25 124.5,122.5 85,122.5 83.75,121.25 83.75,113.75 85,112.5
LINE3_OUT on Inside 1 "INSIDE_1_LINE3_OUT_P056" (solid, remove dead copper, pour order 56): 134.25,126 135.75,127.5 135.75,132.25 134.25,133.75 126.75,133.75 124.5,136 85,136 83.75,134.75 83.75,127.25 85,126
LINE2_OUT on Inside 1 "INSIDE_1_LINE2_OUT_P055" (solid, remove dead copper, pour order 55): 134.25,139.5 135.75,141 135.75,145.75 134.25,147.25 126.75,147.25 124.5,149.5 85,149.5 83.75,148.25 83.75,140.75 85,139.5
LINE1_OUT on Inside 1 "INSIDE_1_LINE1_OUT_P053" (solid, remove dead copper, pour order 53): 134.25,153 135.75,154.5 135.75,159.25 134.25,160.75 126.75,160.75 124.5,163 85,163 83.75,161.75 83.75,154.25 85,153
LINE1_IN on Inside 1 "INSIDE_1_LINE1_IN_P039" (solid, remove dead copper, pour order 39): 76.25,153 77.5,154.25 77.5,161.75 76.25,163 34.75,163 33,161.25 25,161.25 23.75,160 23.75,154.25 25,153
